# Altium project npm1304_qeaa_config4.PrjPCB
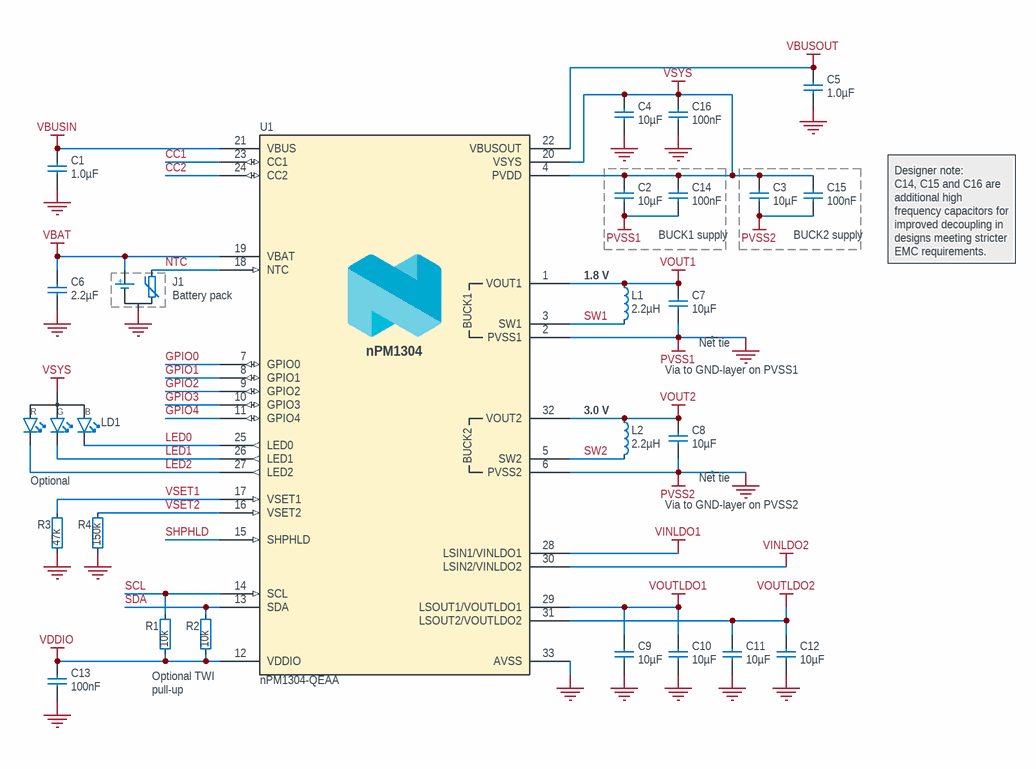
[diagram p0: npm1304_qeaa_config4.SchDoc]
1 sheet, 27 parts. Net scope: global (net labels, ports and power ports of the same name join across sheets).
Board file: npm1304_qeaa_config4.PcbDoc

## Sheet npm1304_qeaa_config4.SchDoc: nPM1304-QEAA Ref. Layout Config. 4
size A4; Revision: 1.0; SheetNumber: 1; SheetTotal: 1; DrawnBy: EISK; DocumentSize: A4; BoardTitle: nPM1304-QEAA Ref. Layout Config. 4; RefLayoutTitle: Full config. + high frequency decoupling; Device: nPM1304-QEAA; Classification: PUBLIC; Config: 4

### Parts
C1  1.0µF  [CAPC1608X06L]
C2  10µF  [CAPC1608X06L]
C3  10µF  [CAPC1608X06L]
C4  10µF  [CAPC1608X06L]
C5  1.0µF  [CAPC1608X06L]
C6  2.2µF  [CAPC1608X06L]
C7  10µF  [CAPC1608X06L]
C8  10µF  [CAPC1608X06L]
C9  10µF  [CAPC1608X06L]
C10  10µF  [CAPC1608X06L]
C11  10µF  [CAPC1608X06L]
C12  10µF  [CAPC1608X06L]
C13  100nF  [CAPC0603X03L_C]
C14  100nF  [CAPC1005X04L]
C15  100nF  [CAPC1005X04L]
C16  100nF  [CAPC1005X04L]
J1  Battery pack  [TP_3x1mm_TH]  (graphical)
L1  2.2µH  [INDC2016X10N]
L2  2.2µH  [INDC2016X10N]
LD1  LED RGB  [LED_RGB_0603]  (value not drawn)  (graphical)
NT1  Net tie  [2 PIN STARPOINT]  (net tie, no BOM)
NT2  Net tie  [2 PIN STARPOINT]  (net tie, no BOM)
R1  10k  [RESC0603X03L_C]
R2  10k  [RESC0603X03L_C]
R3  47k  [RESC0603X03L_C]
R4  150k  [RESC0603X03L_C]
U1  nPM1304-QEAA  [Nordic_QFN50P500X500X90-33N]

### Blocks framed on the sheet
BUCK1 supply: C2 C14
BUCK2 supply: C3 C15

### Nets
GND: C1.1 C4.1 C5.1 C6.1 C9.1 C10.1 C11.1 C12.1 C13.2 C16.2 J1.1(GND) NT1.1 NT2.1 R3.2 R4.2 U1.33(AVSS)
PVSS1: C2.1 C7.1 C14.2 NT1.2 U1.2(PVSS1)
PVSS2: C3.1 C8.1 C15.2 NT2.2 U1.6(PVSS2)
VBAT: C6.2 J1.3(V+) U1.19(VBAT)
VBUSIN: C1.2 U1.21(VBUS)
VBUSOUT: C5.2 U1.22(VBUSOUT)
VDDIO: C13.1 R1.2 R2.2 U1.12(VDDIO)
VINLDO1: U1.28(LSIN1/VINLDO1)
VINLDO2: U1.30(LSIN2/VINLDO2)
VOUT1: C7.2 L1.1 U1.1(VOUT1)
VOUT2: C8.2 L2.1 U1.32(VOUT2)
VOUTLDO1: C9.2 C10.2 U1.29(LSOUT1/VOUTLDO1)
VOUTLDO2: C11.2 C12.2 U1.31(LSOUT2/VOUTLDO2)
VSYS: C2.2 C3.2 C4.2 C14.1 C15.1 C16.1 LD1.4(A) U1.4(PVDD) U1.20(VSYS)
CC1: U1.23(CC1)
CC2: U1.24(CC2)
GPIO0: U1.7(GPIO0)
GPIO1: U1.8(GPIO1)
GPIO2: U1.9(GPIO2)
GPIO3: U1.10(GPIO3)
GPIO4: U1.11(GPIO4)
LED0: LD1.3(C_BLUE) U1.25(LED0)
LED1: LD1.2(C_GREEN) U1.26(LED1)
LED2: LD1.1(C_RED) U1.27(LED2)
NTC: J1.2(NTC) U1.18(NTC)
SCL: R1.1 U1.14(SCL)
SDA: R2.1 U1.13(SDA)
SHPHLD: U1.15(SHPHLD)
SW1: L1.2 U1.3(SW1)
SW2: L2.2 U1.5(SW2)
VSET1: R3.1 U1.17(VSET1)
VSET2: R4.1 U1.16(VSET2)

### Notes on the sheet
- (near L1) 1.8 V
- Designer note:
  C14, C15 and C16 are additional high frequency capacitors for improved decoupling in designs meeting stricter EMC requirements.
- (near L2) 3.0 V
- (near NT1) Via to GND-layer on PVSS1
- Optional LEDs
- (near NT2) Via to GND-layer on PVSS2
- Optional TWI pull-up resistors

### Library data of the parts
C1 = C0603-1µ0-25V-X5R: Capacitor, X5R, ±10%, 25V; Manufacturer: N.A.; Part number NEMS: 100200687; Pad Count: 2; Component Status: Active
C2-C4 C7-C12 = C0603-10µ: Capacitor, X5R, ±20%; Manufacturer: N.A.; Part number IPS: 00000007785; Part number NEMS: 100200275; Note: 6.3V; Artikkelnr Noca: 20039234; Pad Count: 2; Component Status: Active
C5 = C0603-1µ0-10V-X5R: Capacitor, Ceramic, 1.0µF 10V X5R 0603,±10%; Manufacturer: N.A.; Part number NEMS: 100200528; Component Status: Active; Pad Count: 2
C6 = C0603-2.2µ-16V-X7R: Capacitor, Ceramic, X7R, ±10%, 16V; Manufacturer: Taiyo Yuden; Manufacturer Part Number: EMK107BB7225KA-T; Part number NEMS: 100200439; Component Status: Active; Pad Count: 2; Artikkelnr Noca: N.A.
C13 = C0201-100n: Capacitor, X5R, ±10%, 100nF, 16V; Manufacturer: N.A.; Part number IPS: 00000001248, 00000002505; Part number Norautron: 262071862; Part number NEMS: 100200078; Pad Count: 2; Component Status: Active
C14-C16 = C0402-100n-16V-X7R-C0402C104M4RAC7867: Capacitor, Ceramic, X7R, ±20%, 16V; Manufacturer: Kemet; Part number NEMS: 100200504; Component Status: Active; Pad Count: 2; Artikkelnr Noca: N.A.
J1 = Battery_w/NTC_TP: Battery pack with NTC; Manufacturer: N.A.; Part number NEMS: 101800005; Pad Count: 3; Component Status: Active
L1 L2 = L0806-2µ2-2500mA-73mOhm-CIGT201610EH2R2MNE: Inductor, Irms=2.5A, Isat=2.9A, ±20%, DCR=73mΩ; Manufacturer: Samsung Electro-Mechanics America; Part number Norautron: 26521789; Part number NEMS: 100300400; Pad Count: 2; Note: Unshielded Thin Film Inductor; Artikkelnr Noca: N.A.; Component Status: Active
LD1 = APHF1608LSEEQBDZGKC: RGB LED 1.60 mm x 0.80 mm SMD; Manufacturer: Kingbright Company LLC; Part number IPS: 00000001254; Part number Norautron: 26470023; Part number NEMS: 101400123; Pad Count: 4; Note: N.A.; Component Status: Active
NT1 NT2 = 2 pin starpoint: Starpoint; Manufacturer: N.A.; Part number NEMS: 100500603; Pad Count: 2; Component Status: Active
R1 R2 = R0201-10k: Resistor, ±1%, 0.05W; Manufacturer: N.A.; Part number IPS: 00000001255; Part number Norautron: 26107101; Part number NEMS: 100100065; Pad Count: 2; Note: Chip Res 1%; Component Status: Active
R3 = R0201-47k: Resistor, ±1%, 0.05W; Manufacturer: N.A.; Part number IPS: 00000001423; Part number NEMS: 100100076; Component Status: Active; Pad Count: 2; Note: Chip Res 1%
R4 = R0201-150k: Resistor, ±1%, 0.05W; Manufacturer: N.A.; Part number IPS: 00000001422; Part number NEMS: 100100082; Component Status: Active; Pad Count: 2; Note: Chip Res 1%
U1 = nPM1304-QEAA: Li-Ion/Li-Polymer USB-C battery charger with high efficiency buck regulators, LDOs or load switches, LED drivers, TWI and VBUSOUT; Manufacturer: Nordic Semiconductor; Part number NEMS: 102000396; Component Status: Active; Pad Count: 33; Artikkelnr Noca: N.A.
